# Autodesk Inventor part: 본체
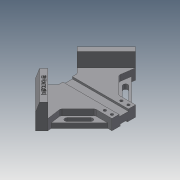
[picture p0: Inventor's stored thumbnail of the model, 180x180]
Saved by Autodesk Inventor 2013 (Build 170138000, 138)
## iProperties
Created: 2020-05
Part Number: 본체
Material: Generic
Document SubType Name: Modeling
Designer: user
Density: 1 g/cm^3
Mass: 211.712 g
Surface Area: 407.173 cm^2
Volume: 211.712 cm^3
Author: user
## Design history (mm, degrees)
sketch "스케치2"
  geometry: L1 (-84.853, 0)-(0, 84.853); L2 (0, 84.853)-(84.853, 0); L3 (84.853, 0)-(0, -84.853); L4 (0, -84.853)-(-84.853, 0); 1 further point
  constraints: 8 end point, 2 horizontal alignment, 2 parallel, 1 vertical alignment
  dimensions: "d5" = 120 distance of L3.end L1.start; "d7" = 120 distance of L2.end L3.end; "d8" = 90 deg angle of L4 L1
extrude "돌출1" new body sketch "스케치2" distance "d9" = 18; taper "d10" = 0 deg
sketch "스케치3"
  geometry: L1 (84.853, 0)-(0, 84.853) reference; L2 (0, 84.853)-(35.355, 49.497); L3 (35.355, 49.497)-(0, 14.142); L4 (0, 14.142)-(-35.355, 49.497); L5 (-35.355, 49.497)-(0, 84.853); 1 further point
  constraints: 8 end point, 2 parallel, 1 perpendicular, 1 point on line
  dimensions: "d11" = 50 distance of L2.end L3.end; "d12" = 50 distance of L1.end L2.end
extrude "돌출2" cut sketch "스케치3" stored distance "d13" = 18; taper "d14" = 0 deg
sketch "스케치4"
  geometry: L1 (-35.355, 49.497)-(-84.853, 0) reference; L2 (84.853, 0)-(35.355, 49.497) reference; L3 (-84.853, 0)-(-35.355, 49.497); L4 (-35.355, 49.497)-(-24.749, 38.891); L5 (-24.749, 38.891)-(-74.246, -10.607); L6 (-74.246, -10.607)-(-84.853, 0); L7 (84.853, 0)-(35.355, 49.497); L8 (35.355, 49.497)-(24.749, 38.891); L9 (24.749, 38.891)-(74.246, -10.607); L10 (74.246, -10.607)-(84.853, 0); 1 further point
  constraints: 16 end point, 6 equal length, 2 perpendicular
  dimensions: "d15" = 15 distance of L1.start L4.end; "d16" = 15 distance of L8.end L2.end
extrude "돌출3" join sketch "스케치4" distance "d17" = 24; taper "d18" = 0 deg
sketch "스케치5"
  geometry: L1 (0, -84.853)-(0, 10.147); L2 (20, -84.853)-(20, -64.853); L3 (-20, -84.853)-(-20, -64.853); L4 (-20, -84.853)-(20, -84.853); L5 (-20, -64.853)-(20, -64.853); 1 further point
  constraints: 10 end point, 3 parallel, 1 midpoint, 1 perpendicular, 1 vertical
  dimensions: "d19" = 95 distance of L1.start L1.end; "d20" = 40 distance of L3.start L2.start; "d21" = 20 distance between parallel lines of L4 L5
extrude "돌출4" cut sketch "스케치5" stored distance "d22" = 24; taper "d23" = 0 deg
sketch "스케치6"
  geometry: L1 (-20, -64.853)-(20, -64.853) reference; L2 (24.749, 38.891)-(0, 14.142) reference; L3 (0, 14.142)-(-24.749, 38.891) reference; L4 (0, -64.853)-(0, 30.147); L5 (0, 30.147)-(-16.005, 30.147); L6 (-16.005, 30.147)-(-16.005, 14.142); L7 (0, 30.147)-(16.005, 30.147); L8 (16.005, 30.147)-(16.005, 14.142); L9 (0, 14.142)-(16.005, 14.142); L10 (0, 14.142)-(-16.005, 14.142); 1 further point
  constraints: 14 end point, 3 perpendicular, 2 point on line, 1 midpoint
  dimensions: "d24" = 95 distance of L4.start L4.end; "d25" = 16.00505 distance of L4.end L7.end; "d26" = 16.00505 distance of L7.end L8.end; "d27" = 16.00505 distance of L2.end L6.end; "d28" = 16.00505 distance of L2.end L8.end
extrude "돌출5" join sketch "스케치6" distance "d29" = 18; taper "d30" = 0 deg
sketch "스케치7"
  geometry: L1 (-20, -64.853)-(20, -64.853) reference; L2 (16.005, 30.147)-(-16.005, 30.147) reference; L3 (0, -64.853)-(0, 30.147); L4 (8, -64.853)-(8, 30.147); L5 (-8, -64.853)-(-8, 30.147); L6 (-8, 30.147)-(8, 30.147); L7 (8, -64.853)-(-8, -64.853); 2 further points
  constraints: 10 end point, 4 midpoint, 2 parallel, 1 collinear, 1 perpendicular
  dimensions: "d31" = 16 distance of L5.end L4.end; "d33" = 95 distance of L4.start L4.end
extrude "돌출6" cut sketch "스케치7" distance "d34" = 3.5; taper "d35" = 0 deg
sketch "스케치8"
  geometry: L1 (20, 64.853)-(-20, 64.853) reference; L2 (-16.005, -30.147)-(16.005, -30.147) reference; L3 (0, -30.147)-(0, 64.853); L4 (6, -30.147)-(6, 64.853); L5 (-6, -30.147)-(-6, 64.853); L6 (-6, 64.853)-(6, 64.853); L7 (6, -30.147)-(-6, -30.147); 2 further points
  constraints: 10 end point, 4 midpoint, 2 parallel, 1 perpendicular
  dimensions: "d36" = 12 distance between parallel lines of L4 L5; "d38" = 95 distance of L4.start L4.end; "d39" = 95 distance of L5.start L5.end
extrude "돌출7" cut sketch "스케치8" distance "d40" = 3; taper "d41" = 0 deg
sketch "스케치11"
  geometry: L1 (20, 64.853)-(6, 64.853) reference; L2 (-6, 64.853)-(-20, 64.853) reference; 5 further points
  constraints: 2 vertical alignment
  dimensions: "d50" = 28 distance of point (14, 58.853) point (-14, 58.853); "d52" = 6 distance from line of L2 point (-14, 58.853); "d53" = 6 distance from line of point (14, 58.853) L1; "d54" = 12 distance of point (14, 58.853) point (14, 46.853); "d55" = 12 distance of point (-14, 58.853) point (-14, 46.853); "d56" = 14 horizontal distance of point (-14, 58.853) point (0, 0)
hole "구멍1" sketch "스케치11" at (-14, 58.853), (-14, 46.853), (14, 58.853), (14, 46.853) diameter "d57" = 4.5; stored, may be unused: countersink angle "d61" = 90 deg, drill point angle "d63" = 118 deg; dims "d58" = 6, "d59" = 8, "d60" = 10, "d62" = 8
sketch "스케치12"
  geometry: L1 (-74.246, -10.607)-(-20, -64.853) reference; L2 (-20, -64.853)-(-8, -64.853) reference; L3 (-20, -64.853)-(-20, -36.569); L4 (-20, -36.569)-(-49.497, -7.071); L5 (-49.497, -7.071)-(-74.246, -10.607); L6 (-35.355, 49.497)-(-84.853, 0) reference; L7 (-74.246, -10.607)-(-20, -64.853); 1 further point
  constraints: 8 end point, 2 perpendicular, 1 parallel
  dimensions: "d64" = 20 distance from line of L1 L4.end; "d65" = 30 distance from line of L6 L4.end
extrude "돌출8" cut sketch "스케치12" distance "d66" = 10; taper "d67" = 0 deg
sketch "스케치13"
  geometry: L1 (-20, -64.853)-(-74.246, -10.607) reference; L2 (-20, -36.569)-(-20, -64.853) reference; L3 (-49.497, -7.071)-(-20, -36.569) reference; L4 (-74.246, -10.607)-(-49.497, -7.071) reference; L5 (-68.059, -9.723)-(-20, -57.782); L6 (-68.059, -9.723)-(-74.246, -10.607); L7 (-20, -64.853)-(-20, -57.782); L8 (-20, -64.853)-(-74.246, -10.607); 1 further point
  constraints: 8 end point, 2 collinear, 2 point on line, 1 parallel
  dimensions: "d68" = 5 distance between parallel lines of L1 L5
extrude "돌출9" cut sketch "스케치13" stored distance "d69" = 10; taper "d70" = 0 deg
sketch "스케치14"
  geometry: L1 (-49.497, -7.071)-(-20, -36.569) reference; L2 (-52.326, -21.213)-(-46.669, -15.556); L3 (-46.669, -15.556)-(-26.87, -35.355); L4 (-26.87, -35.355)-(-32.527, -41.012); L5 (-32.527, -41.012)-(-52.326, -21.213); L6 (-35.355, 49.497)-(-84.853, 0) reference; L7 (-84.853, 0)-(-74.246, -10.607) reference; C1 r 4 at (-29.698, -38.184); A1 r 4 centre (-49.497, -18.385) between (-52.326, -21.213) and (-46.669, -15.556); 2 further points
  constraints: 8 end point, 2 centre point, 2 parallel, 2 perpendicular, 2 point on circle, 1 coincident, 1 midpoint
  dimensions: "d71" = 8 diameter of A1; "d72" = 8 diameter of C1; "d73" = 8 distance of L2.start L2.end; "d74" = 38 distance from line of L6 A1.centre; "d75" = 28 distance of C1.centre A1.centre; "d91" = 12 distance from line of L7 A1.centre
extrude "돌출10" cut sketch "스케치14" stored distance "d77" = 10; taper "d78" = 0 deg
chamfer "모따기1" distance "d79" = 5; stored, may be unused: second distance "d80" = 15, angle "d81" = 45 deg
chamfer "모따기2" distance "d82" = 5; stored, may be unused: second distance "d83" = 15, angle "d84" = 45 deg
fillet "모깎기1" dims "d85" = 5
fillet "모깎기2" dims "d86" = 5
sketch "스케치16"
  geometry: L1 (-74.246, -10.607)-(-24.749, 38.891) reference; L2 (-24.749, 38.891)-(-31.82, 45.962) reference; 2 further points
  constraints: 1 other
  dimensions: "d87" = 35 distance from line of L2 point (-53.033, 17.678); "d88" = 5 distance from line of L1 point (-53.033, 17.678)
feature "엠보싱1" sketch "스케치16" dims "d7" = 120, "d15" = 15, "d89" = 0.5, "d90" = 0
node "솔리드1"
mirror "대칭1"
